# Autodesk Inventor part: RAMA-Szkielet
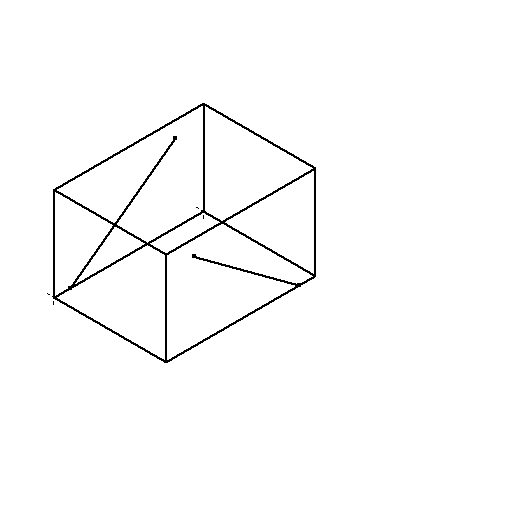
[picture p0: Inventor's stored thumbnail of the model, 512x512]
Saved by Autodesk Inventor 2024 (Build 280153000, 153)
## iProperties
Company: ATC
Created: 2023-03
Part Number: RAMA-Szkielet
Document SubType Name: Modeling
Designer: Andrzej Jaskulski
Density: 1 g/cm^3
Stock Number: RAMA-Szkielet
Material: Kurs-AJ
Appearance: Kurs-AJ
Checked By: A.J.
Engr Approved By: Andrzej Jaskulski
Mfg Approved By: Andrzej Jaskulski
Authority: A.J.
Wy: 200,000 mm
Sz: 240,000 mm
Dl: 320,000 mm
Title: A.J.: Kurs R2024-MEP
Author: Andrzej Jaskulski
Revision Number: 1/24
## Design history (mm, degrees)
node "Płaszczyzna konstrukcyjna1"
node "Płaszczyzna konstrukcyjna3"
node "Płaszczyzna konstrukcyjna4"
node "Płaszczyzna konstrukcyjna5"
sketch "Szkic 3D1"
sketch "Szkic 3D2"
node "Korpusy bryłowe"
node "Korpusy powierzchniowe"
sketch "Szkic1"
  geometry: L1 (0, 0)-(0, -320); L2 (0, -320)-(240, -320); L3 (240, -320)-(240, 0); L4 (240, 0)-(0, 0)
  constraints: 8 end point, 2 parallel, 1 perpendicular, 1 vertical, 1 other
  dimensions: "d0" = 320 distance of L2.end L3.end (= Dl); "d1" = 240 distance of L3.end L1.start (= Sz)
sketch "Szkic2"
  geometry: L1 (0, 0)-(0, -320); L2 (0, -320)-(240, -320); L3 (240, -320)-(240, 0); L4 (240, 0)-(0, 0)
  constraints: 8 end point, 2 parallel, 1 perpendicular, 1 vertical, 1 other
  dimensions: "d9" = 320 distance of L2.end L3.end (= Dl); "d10" = 240 distance of L3.end L1.start (= Sz)
sketch "Szkic3"
  geometry: L1 (0, 0)-(240, 0); L2 (240, 0)-(240, -200); L3 (240, -200)-(0, -200); L4 (0, -200)-(0, 0)
  constraints: 8 end point, 2 parallel, 1 horizontal, 1 perpendicular, 1 other
  dimensions: "d4" = 240 distance of L2.end L3.end (= Sz); "d5" = 200 distance of L3.end L1.start (= Wy)
sketch "Szkic4"
  geometry: L1 (-60, -60)-(180, -60); L2 (180, -60)-(180, -260); L3 (180, -260)-(-60, -260); L4 (-60, -260)-(-60, -60)
  constraints: 8 end point, 2 parallel, 1 horizontal, 1 perpendicular, 1 other
  dimensions: "d7" = 240 distance of L2.end L3.end (= Sz); "d8" = 200 distance of L3.end L1.start (= Wy)
other parameters: "Dl" = 320 [user parameter; used in 3 equation terms], "Sz" = 240 [user parameter; used in 4 equation terms], "Wy" = 200 [user parameter; used in 3 equation terms]
